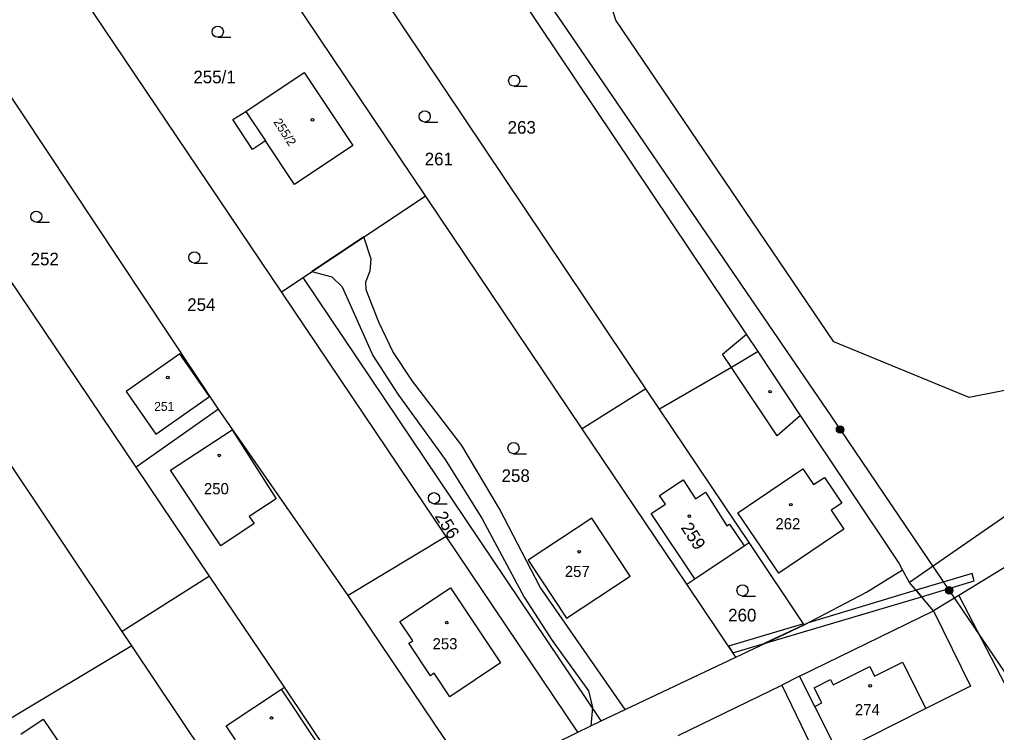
# Model space of a CAD drawing. Extents: x -504988 to -494607, y -1123820 to -1114018.
# Drawn here: x -496996.2 to -496865, y -1120218.5 to -1120122.8 of the extents above; entities that cross this region are included whole.
import ezdxf

# ---------------------------------------------------------------- set-up
doc = ezdxf.new("R2010")
doc.units = 0
for name, color, linetype in [('Hranice parcel', 7, 'Continuous'), ('Parcelní čísla', 7, 'Continuous'), ('Poz předměty', 7, 'Continuous'), ('Vnitřní kresba', 7, 'Continuous'), ('Věcná břemena k části', 7, 'Continuous'), ('Značky budov', 7, 'Continuous'), ('Značky kultur', 7, 'Continuous')]:
    doc.layers.add(name, color=color, linetype=linetype)

msp = doc.modelspace()

# ---------------------------------------------------------------- linework, layer by layer
at = {"layer": 'Hranice parcel'}
for p, q in [((-496912.08, -1120172.35), (-496962.9, -1120096.6)), ((-496941.67, -1120146.42), (-496972.04, -1120101.28)), ((-496961.03, -1120159.32), (-496993.01, -1120111.83)), ((-496969.48, -1120175.1), (-497007.06, -1120118.48)), ((-496980.54, -1120182.87), (-497019.85, -1120124.5)), ((-496958.12, -1120157.38), (-496941.67, -1120146.42)), ((-496920.64, -1120177.7), (-496941.67, -1120146.42)), ((-496982.41, -1120204.92), (-497016.94, -1120153.36)), ((-496961.03, -1120159.32), (-496958.12, -1120157.38)), ((-496918.08, -1120216.91), (-496958.12, -1120157.38)), ((-496938.91, -1120192.18), (-496961.03, -1120159.32)), ((-496831.83, -1120167.28), (-496876.68, -1120198.34)), ((-496912.08, -1120172.35), (-496920.64, -1120177.7)), ((-496910.27, -1120175.06), (-496912.08, -1120172.35)), ((-496827.7, -1120174.13), (-496870.08, -1120200.09)), ((-496969.48, -1120175.1), (-496980.54, -1120182.87)), ((-496952.05, -1120200.09), (-496969.48, -1120175.1)), ((-496898.23, -1120193), (-496910.27, -1120175.06)), ((-496906.59, -1120198.6), (-496920.64, -1120177.7)), ((-496970.7, -1120197.49), (-496980.54, -1120182.87)), ((-496938.91, -1120192.18), (-496952.05, -1120200.09)), ((-496921.22, -1120218.43), (-496938.91, -1120192.18)), ((-496890.84, -1120204.02), (-496898.23, -1120193)), ((-496876.68, -1120198.34), (-496877.64, -1120196.65)), ((-496970.7, -1120197.49), (-496982.41, -1120204.92)), ((-496960.64, -1120212.42), (-496970.7, -1120197.49)), ((-496873.49, -1120202.18), (-496876.68, -1120198.34)), ((-496900.02, -1120208.36), (-496906.59, -1120198.6)), ((-496935.1, -1120225.25), (-496952.05, -1120200.09)), ((-496870.08, -1120200.09), (-496873.49, -1120202.18)), ((-496870.08, -1120200.09), (-496852.99, -1120233.15)), ((-496891.46, -1120210.95), (-496873.49, -1120202.18)), ((-496981.11, -1120206.87), (-496982.41, -1120204.92)), ((-496900.02, -1120208.36), (-496890.84, -1120204.02)), ((-496981.11, -1120206.87), (-496998.2, -1120217.1)), ((-496970.71, -1120222.4), (-496981.11, -1120206.87)), ((-496918.08, -1120216.91), (-496900.02, -1120208.36)), ((-496891.46, -1120210.95), (-496893.86, -1120212.12)), ((-496947.9, -1120231.34), (-496960.64, -1120212.42)), ((-496907.75, -1120218.89), (-496893.86, -1120212.12)), ((-496893.86, -1120212.12), (-496877.58, -1120245.67)), ((-496921.22, -1120218.43), (-496918.08, -1120216.91)), ((-496935.1, -1120225.25), (-496921.22, -1120218.43))]:
    msp.add_line(p, q, dxfattribs=at)
for points in [[(-496699.03, -1120160.06), (-496708.47, -1120148.74), (-496711.13, -1120142.51), (-496710.85, -1120118.38), (-496716.62, -1120106.84), (-496726.56, -1120101.15), (-496737.66, -1120100.11), (-496748.22, -1120102.83), (-496762, -1120119.74), (-496835.05, -1120162.21), (-496849.44, -1120169.69), (-496868.7, -1120173.5), (-496886.87, -1120166.04), (-496916.11, -1120122.87), (-496925.75, -1120092.26), (-496930.84, -1120083.06), (-496935.68, -1120078.2)], [(-496897.01, -1120167.36), (-496898.6, -1120165), (-496946.77, -1120093.09)], [(-496967.56, -1120136.18), (-496965.82, -1120135.1), (-496957.99, -1120129.88), (-496951.44, -1120139.7), (-496959.26, -1120144.93), (-496963.17, -1120139.07)], [(-496963.17, -1120139.07), (-496964.92, -1120140.23), (-496967.56, -1120136.18)], [(-496970.67, -1120173.37), (-496974.69, -1120167.64), (-496981.9, -1120172.71), (-496977.88, -1120178.43), (-496970.67, -1120173.37)], [(-496897.01, -1120167.36), (-496900.59, -1120169.48), (-496910.27, -1120175.06)], [(-496877.64, -1120196.65), (-496878.19, -1120195.64), (-496891.32, -1120175.93), (-496897.01, -1120167.36)], [(-496919.34, -1120189.7), (-496927.9, -1120195.34), (-496922.76, -1120203.15), (-496914.19, -1120197.51), (-496919.34, -1120189.7)], [(-496906.59, -1120198.6), (-496905.51, -1120197.88), (-496898.89, -1120193.44), (-496898.23, -1120193)], [(-496890.84, -1120204.02), (-496882.47, -1120199.64), (-496877.64, -1120196.65)], [(-496873.49, -1120202.18), (-496868.5, -1120212.26), (-496874.49, -1120215.28), (-496886.29, -1120221.22), (-496889.43, -1120214.99), (-496891.46, -1120210.95)], [(-496956.39, -1120235.42), (-496963.68, -1120224.81), (-496956.24, -1120219.88), (-496961.02, -1120212.67), (-496960.64, -1120212.42)]]:
    msp.add_lwpolyline(points, dxfattribs=at)
at = {"layer": 'Poz předměty'}
for p, q in [((-496942.22, -1120095.55), (-496886.02, -1120177.82)), ((-496886.02, -1120177.82), (-496871.37, -1120199.41)), ((-496871.37, -1120199.41), (-496831.27, -1120258.77))]:
    msp.add_line(p, q, dxfattribs=at)
for centre, radius in [((-496886.02, -1120177.82), 0.5), ((-496886.02, -1120177.82), 0.4), ((-496886.02, -1120177.82), 0.3), ((-496886.02, -1120177.82), 0.2), ((-496886.02, -1120177.82), 0.1), ((-496871.37, -1120199.41), 0.5), ((-496871.37, -1120199.41), 0.4), ((-496871.37, -1120199.41), 0.3), ((-496871.37, -1120199.41), 0.2), ((-496871.37, -1120199.41), 0.1)]:
    msp.add_circle(centre, radius, dxfattribs=at)
at = {"layer": 'Vnitřní kresba'}
for p, q in [((-496965.82, -1120135.1), (-496963.17, -1120139.07)), ((-496901.8, -1120167.68), (-496898.6, -1120165)), ((-496900.59, -1120169.48), (-496901.8, -1120167.68)), ((-496894.47, -1120178.65), (-496900.59, -1120169.48)), ((-496891.32, -1120175.93), (-496894.47, -1120178.65)), ((-496975.93, -1120183.29), (-496967.67, -1120177.87)), ((-496967.67, -1120177.87), (-496961.73, -1120187.12)), ((-496969.16, -1120193.44), (-496975.93, -1120183.29)), ((-496899.73, -1120189.01), (-496891.01, -1120183.09)), ((-496891.01, -1120183.09), (-496889.57, -1120185.21)), ((-496910.26, -1120186.68), (-496907.09, -1120184.55)), ((-496907.09, -1120184.55), (-496905.44, -1120187.1)), ((-496889.57, -1120185.21), (-496888.13, -1120184.24)), ((-496888.13, -1120184.24), (-496885.79, -1120187.68)), ((-496909.48, -1120187.84), (-496910.26, -1120186.68)), ((-496905.44, -1120187.1), (-496904.11, -1120186.21)), ((-496904.11, -1120186.21), (-496901.22, -1120190.76)), ((-496961.73, -1120187.12), (-496965.35, -1120189.5)), ((-496911.37, -1120189.1), (-496909.48, -1120187.84)), ((-496885.79, -1120187.68), (-496887.23, -1120188.66)), ((-496905.51, -1120197.88), (-496911.37, -1120189.1)), ((-496894.23, -1120197.12), (-496899.73, -1120189.01)), ((-496887.23, -1120188.66), (-496885.5, -1120191.21)), ((-496964.71, -1120190.43), (-496969.16, -1120193.44)), ((-496965.35, -1120189.5), (-496964.71, -1120190.43)), ((-496901.22, -1120190.76), (-496900.86, -1120190.52)), ((-496900.86, -1120190.52), (-496898.89, -1120193.44)), ((-496885.5, -1120191.21), (-496894.23, -1120197.12)), ((-496945.14, -1120203.6), (-496938.33, -1120199.07)), ((-496938.33, -1120199.07), (-496931.61, -1120209.15)), ((-496943.41, -1120206.19), (-496945.14, -1120203.6)), ((-496943.91, -1120206.52), (-496943.41, -1120206.19)), ((-496941.01, -1120210.88), (-496943.91, -1120206.52)), ((-496931.61, -1120209.15), (-496938.41, -1120213.69)), ((-496886.96, -1120212.11), (-496882.04, -1120209.65)), ((-496882.04, -1120209.65), (-496881.39, -1120210.94)), ((-496881.39, -1120210.94), (-496877.63, -1120209.05)), ((-496877.63, -1120209.05), (-496874.49, -1120215.28)), ((-496940.51, -1120210.55), (-496941.01, -1120210.88)), ((-496938.41, -1120213.69), (-496940.51, -1120210.55)), ((-496889.5, -1120212.49), (-496887.32, -1120211.4)), ((-496887.32, -1120211.4), (-496886.96, -1120212.11)), ((-496968.46, -1120217.6), (-496961.02, -1120212.67)), ((-496888.48, -1120214.51), (-496889.5, -1120212.49)), ((-496889.43, -1120214.99), (-496888.48, -1120214.51)), ((-496996.01, -1120218.72), (-496993.02, -1120216.7)), ((-496993.02, -1120216.7), (-496990.11, -1120221)), ((-496967.22, -1120219.47), (-496968.46, -1120217.6))]:
    msp.add_line(p, q, dxfattribs=at)
at = {"layer": 'Věcná břemena k části'}
for points in [[(-496919.47, -1120217.58), (-496918.08, -1120216.91), (-496914.89, -1120215.4), (-496926.29, -1120198.99), (-496931.73, -1120188.45), (-496936.79, -1120179.94), (-496943.45, -1120171.33), (-496946.07, -1120167.33), (-496947.95, -1120163.42), (-496949.65, -1120159.05), (-496949.69, -1120157.98), (-496949.1, -1120156.52), (-496948.97, -1120154.95), (-496949.95, -1120151.94), (-496956.93, -1120156.59), (-496954.27, -1120157.29), (-496952.88, -1120158.65), (-496948.75, -1120167.88), (-496945.41, -1120173.07), (-496939.05, -1120181.82), (-496934.07, -1120189.81), (-496928.42, -1120200.32), (-496924.66, -1120206.13), (-496919.82, -1120212.91), (-496919.26, -1120215.16)], [(-496875.82, -1120199.38), (-496875.08, -1120200.26), (-496868.01, -1120198.13), (-496868.26, -1120197.13)], [(-496896.19, -1120206.55), (-496875.08, -1120200.26), (-496875.82, -1120199.38), (-496890.32, -1120203.75), (-496890.84, -1120204.02)], [(-496900.4, -1120207.79), (-496896.19, -1120206.55), (-496890.84, -1120204.02), (-496890.92, -1120203.9), (-496900.99, -1120206.92)]]:
    msp.add_lwpolyline(points, close=True, dxfattribs=at)
at = {"layer": 'Značky budov'}
for centre in [(-496956.86, -1120136.24), (-496976.29, -1120170.83), (-496895.42, -1120172.73), (-496969.38, -1120181.29), (-496892.62, -1120187.9), (-496906.26, -1120189.44), (-496921.05, -1120194.22), (-496938.84, -1120203.74), (-496881.97, -1120212.22), (-496962.36, -1120216.54)]:
    msp.add_circle(centre, 0.175, dxfattribs=at)
at = {"layer": 'Značky kultur'}
for p, q in [((-496969.58, -1120125.15), (-496967.83, -1120125.15)), ((-496929.78, -1120131.73), (-496928.03, -1120131.73)), ((-496941.79, -1120136.53), (-496940.04, -1120136.53)), ((-496993.94, -1120149.98), (-496992.19, -1120149.98)), ((-496972.72, -1120155.46), (-496970.97, -1120155.46)), ((-496929.87, -1120181.06), (-496928.12, -1120181.06)), ((-496940.55, -1120187.78), (-496938.8, -1120187.78)), ((-496899.12, -1120200.17), (-496897.37, -1120200.17))]:
    msp.add_line(p, q, dxfattribs=at)
for centre in [(-496969.58, -1120124.4), (-496929.78, -1120130.98), (-496941.79, -1120135.78), (-496993.94, -1120149.23), (-496972.72, -1120154.71), (-496929.87, -1120180.31), (-496940.55, -1120187.03), (-496899.12, -1120199.42)]:
    msp.add_circle(centre, 0.75, dxfattribs=at)

# ---------------------------------------------------------------- texts
at = {"layer": 'Parcelní čísla'}
for s, height, p in [('255/1', 1.7, (-496972.86, -1120131.33)), ('263', 1.7, (-496930.66, -1120138.09)), ('261', 1.7, (-496941.79, -1120142.34)), ('252', 1.7, (-496994.71, -1120155.77)), ('254', 1.7, (-496973.68, -1120161.89)), ('251', 1.2, (-496978.11, -1120175.31)), ('258', 1.7, (-496931.47, -1120184.86)), ('250', 1.5, (-496971.44, -1120186.51)), ('262', 1.5, (-496894.7, -1120191.22)), ('257', 1.5, (-496922.98, -1120197.62)), ('260', 1.7, (-496901.05, -1120203.59)), ('253', 1.5, (-496940.74, -1120207.33)), ('274', 1.5, (-496884.03, -1120216.19))]:
    msp.add_text(s, height=height, dxfattribs=at).set_placement(p)
for s, height, rotation, p in [('255/2', 1.2, 303, (-496962.16, -1120136.52)), ('256', 1.7, 302, (-496940.49, -1120189.46)), ('259', 1.7, 303, (-496907.46, -1120190.98))]:
    msp.add_text(s, height=height, rotation=rotation, dxfattribs=at).set_placement(p)

doc.saveas('drawing.dxf')
